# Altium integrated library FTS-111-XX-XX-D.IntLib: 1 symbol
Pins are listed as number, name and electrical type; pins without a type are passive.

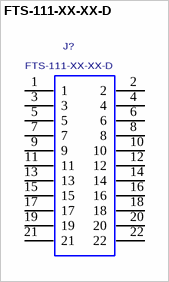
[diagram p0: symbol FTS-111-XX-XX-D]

## FTS-111-XX-XX-D
designator J?
.050 X .050 C.L. LOW PROFILE TERMINAL STRIP ASSEMBLY.; MANUFACTURER: SAMTEC
footprint FTS-111-XX-XX-D
pins: 1, 2, 3, 4, 5, 6, 7, 8, 9, 10, 11, 12, 13, 14, 15, 16, 17, 18, 19, 20, 21, 22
